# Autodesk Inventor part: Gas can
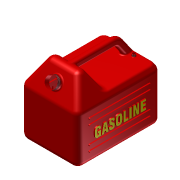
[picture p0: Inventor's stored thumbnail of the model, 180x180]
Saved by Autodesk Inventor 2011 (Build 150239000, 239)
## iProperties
Created: 2009-12
Part Number: Gas can
Document SubType Name: Modeling
Designer: t_jahrl
Mass: 40000 g
Surface Area: 7200 cm^2
Volume: 40000 cm^3
Density: 1 g/cm^3
Author: t_jahrl
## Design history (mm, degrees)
sketch "Sketch1"
  geometry: L1 (-120, 175)-(120, 175); L2 (120, 175)-(120, -175); L3 (120, -175)-(-120, -175); L4 (-120, -175)-(-120, 175); L5 (-120, 175)-(120, -175); 2 further points
  constraints: 10 end point, 2 parallel, 1 coincident, 1 horizontal, 1 midpoint, 1 perpendicular
  dimensions: "d0" = 240 distance of L1.start L1.end; "d1" = 350 distance of L3.end L1.start
extrude "Extrusion1" new body sketch "Sketch1" distance "d2" = 200; taper "d3" = 0 deg
sketch "Sketch21"
  geometry: L1 (-120, 175)-(120, 175) reference; L2 (120, -175)-(-120, -175) reference; L3 (120, 175)-(120, -175) reference; L4 (-120, -175)-(-120, 175) reference; 1 further point
extrude "Extrusion4" join sketch "Sketch21" distance "d473" = 100; taper "d474" = -30 deg
sketch "Sketch22"
  geometry: L1 (175, 200)-(117.265, 300) reference; L2 (117.265, 300)-(-117.265, 300) reference; L3 (163.453, 220)-(117.265, 300); L4 (-87.265, 300)-(-41.077, 220); L5 (-41.077, 220)-(163.453, 220); L6 (117.265, 300)-(-87.265, 300); 1 further point
  constraints: 8 end point, 2 collinear, 2 parallel, 2 point on line
  dimensions: "d524" = 20 distance from line of L1.start L5; "d525" = 30 distance of L2.end L4.start
extrude "Extrusion5" cut sketch "Sketch22" stored distance "d485" = 50; taper "d486" = 0 deg
sketch "Sketch23"
  geometry: L1 (100.953, 0)-(125.953, 0); L2 (125.953, 0)-(125.953, -25); L3 (125.953, -25)-(100.953, -25); L4 (100.953, -25)-(100.953, 0); L5 (113.453, 7.265)-(113.453, -25); L6 (0, 0)-(226.906, 0); L7 (0, 0)-(216.906, 0) reference; A1 r 12.5 centre (113.453, -25) between (100.953, -25) and (125.953, -25)
  constraints: 12 end point, 2 collinear, 2 parallel, 2 point on circle, 1 centre point, 1 coincident, 1 horizontal, 1 midpoint, 1 perpendicular, 1 vertical
  dimensions: "d488" = 25 distance of L1.start L1.end; "d489" = 25 distance of L1.end L2.end (derived)
sketch "Sketch24"
  geometry: L1 (163.453, 220)-(122.366, 278.679); L2 (81.408, 300)-(-87.265, 300); L3 (175, 200)-(-175, 200) reference; A1 r 50 centre (81.408, 250) between (122.366, 278.679) and (81.408, 300); 1 further point
  constraints: 4 end point, 2 point on circle, 2 tangent, 1 centre point, 1 parallel
  dimensions: "d526" = 50 radius of A1
sweep "Sweep2" sketch "Sketch23", "Sketch24" dims "d492" = 0
sketch "Sketch25"
  geometry: L1 (182.265, 115.47)-(57.735, 115.47) reference; L2 (240, 0)-(0, 0) reference; L3 (120, 115.47)-(120, 0); L4 (216.132, 57.735)-(23.868, 57.735); L5 (240, 0)-(182.265, 115.47) reference; L6 (0, 0)-(57.735, 115.47) reference; C1 r 25 at (120, 57.735); 1 further point
  constraints: 4 end point, 4 midpoint, 1 centre point
  dimensions: "d493" = 50 diameter of C1
extrude "Extrusion6" join sketch "Sketch25" distance "d494" = 25; taper "d495" = 0 deg
sketch "Sketch26"
  geometry: L1 (108.028, 204.53)-(197.612, 204.53); L2 (125.953, 204.53)-(216.906, 204.53) reference; L3 (125.953, 204.53)-(125.953, 179.53) reference; C1 r 7 at (145.953, 184.53); 1 further point
  constraints: 2 end point, 1 centre point, 1 collinear
  dimensions: "d503" = 14 diameter of C1; "d509" = 20 distance from line of C1.centre L1; "d527" = 20 distance from line of C1.centre L3
extrude "Extrusion7" join sketch "Sketch26" distance "d504" = 10; taper "d505" = 0 deg
fillet "Fillet2" dims "d496" = 25
fillet "Fillet3" dims "d497" = 10
fillet "Fillet5" dims "d499" = 5
sketch "Sketch27"
  geometry: L1 (0, 0)-(0, 300) reference; L2 (168.301, 0)-(0, 0) reference; L3 (168.301, 300)-(168.301, 0) reference; L4 (65.771, 40)-(65.771, 259.07); L5 (65.771, 259.07)-(108.301, 259.07); L6 (108.301, 259.07)-(108.301, 40); L7 (108.301, 40)-(65.771, 40); 1 further point
  constraints: 1 parallel, 2 other
  dimensions: "d530" = 40 distance from line of L6.end L2; "d531" = 60 distance from line of L6.end L3
emboss "Emboss6" sketch "Sketch27" dims "d0" = 240, "d1" = 350, "d532" = 5, "d533" = 0
sketch "Sketch28" dims "d3" = 0, "d543" = 10
  geometry: L1 (0, 300)-(168.301, 300) reference; L2 (0, 0)-(0, 300) reference; L3 (168.301, 0)-(0, 0) reference; L4 (28, 24)-(28, 276); L5 (20, 276)-(20, 24); L6 (44, 276)-(44, 24); L7 (52, 24)-(52, 276); L8 (68, 276)-(68, 24); L9 (76, 24)-(76, 276); L10 (92, 276)-(92, 24); L11 (100, 24)-(100, 276); L12 (116, 276)-(116, 24); L13 (124, 24)-(124, 276); L14 (140, 276)-(140, 24); L15 (148, 24)-(148, 276); A1 r 4 centre (24, 24) between (20, 24) and (28, 24); A2 r 4 centre (24, 276) between (28, 276) and (20, 276); A3 r 4 centre (48, 24) between (44, 24) and (52, 24); A4 r 4 centre (48, 276) between (52, 276) and (44, 276); A5 r 4 centre (72, 24) between (68, 24) and (76, 24); A6 r 4 centre (72, 276) between (76, 276) and (68, 276); A7 r 4 centre (96, 24) between (92, 24) and (100, 24); A8 r 4 centre (96, 276) between (100, 276) and (92, 276); A9 r 4 centre (120, 24) between (116, 24) and (124, 24); A10 r 4 centre (120, 276) between (124, 276) and (116, 276); A11 r 4 centre (144, 24) between (140, 24) and (148, 24); A12 r 4 centre (144, 276) between (148, 276) and (140, 276); 1 further point
  constraints: 24 end point, 24 point on circle, 12 centre point, 4 tangent, 1 horizontal, 1 parallel, 50 other
  dimensions: "d534" = 4 radius of A2; "d535" = 24 distance from line of A1.centre L3; "d536" = 24 distance from line of L1 A2.centre (derived); "d537" = 24 distance from line of A1.centre L2; "d540" = 24 distance of A1.centre A3.centre
extrude "Extrusion8" join sketch "Sketch28" distance "d545" = 5; taper "d546" = 0 deg
pattern_circular "Circular Pattern1" dims angle "d548" = 360 deg
thread "Thread1" dims "d501" = 15, "d502" = 5
fillet "Fillet6" dims "d508" = 2
shell "Shell1" dims "d500" = 1.5
thread "Thread3" dims "d528" = 8, "d529" = 0
body "Solid1"
node "Projected Loop10"
node "Projected Loop11"
other parameters: "d295" = 11.90476 (derived)
